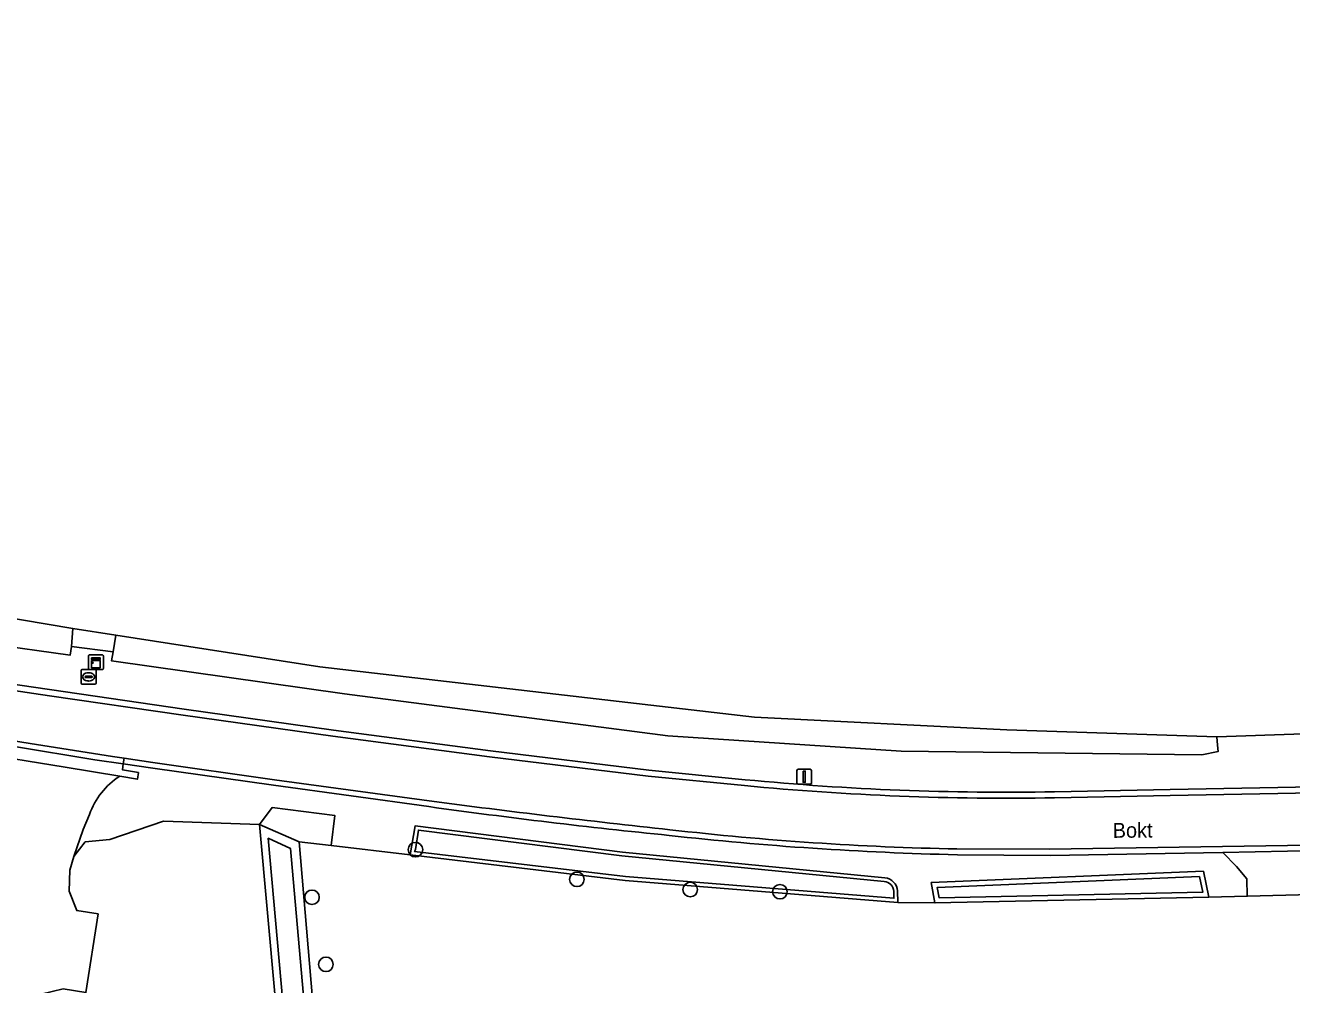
# Model space of a CAD drawing. Extents: x 162510 to 163918, y 388494 to 389774.
# Drawn here: x 162682.9 to 162767.9, y 389035.7 to 389100.2 of the extents above; entities that cross this region are included whole.
import ezdxf

# ---------------------------------------------------------------- set-up
doc = ezdxf.new("R2010")
doc.units = 0
for name, color, linetype in [('IMGEO_Boom', 7, 'Continuous'), ('IMGEO_Bouwland', 7, 'Continuous'), ('IMGEO_Duiker', 7, 'Continuous'), ('IMGEO_Erf', 7, 'Continuous'), ('IMGEO_Groenvoorziening', 7, 'Continuous'), ('IMGEO_Kast', 7, 'Continuous'), ('IMGEO_Lichtmast', 7, 'Continuous'), ('IMGEO_Oever', 7, 'Continuous'), ('IMGEO_Openbare_ruimte_label', 7, 'Continuous'), ('IMGEO_Rijbaan_lokaal_gesloten', 7, 'Continuous'), ('IMGEO_Rijbaan_lokaal_halfverhard', 7, 'Continuous'), ('IMGEO_Rijbaan_lokaal_onverhard', 7, 'Continuous'), ('IMGEO_Rioolput', 7, 'Continuous'), ('IMGEO_Voetpad_halfverhard', 7, 'Continuous'), ('IMGEO_Waterloop', 7, 'Continuous')]:
    doc.layers.add(name, color=color, linetype=linetype)

msp = doc.modelspace()

# ---------------------------------------------------------------- linework, layer by layer
at = {"layer": 'IMGEO_Boom'}
for centre in [(162709.078, 389044.8), (162719.925, 389042.806), (162702.13, 389041.6), (162727.531, 389042.116), (162733.555, 389041.974), (162703.062, 389037.094)]:
    msp.add_circle(centre, 0.489, dxfattribs=at)
at = {"layer": 'IMGEO_Bouwland'}
msp.add_lwpolyline([(162655.166, 389107.621), (162652.745, 389083.952), (162650.857, 389065.794), (162651.566, 389065.632), (162653.989, 389065.078), (162657.8, 389064.433), (162686.069, 389059.649), (162688.964, 389059.201), (162702.649, 389057.082), (162731.841, 389053.7), (162748.803, 389052.862), (162762.9, 389052.38), (162768.724, 389052.581), (162789.49, 389053.299), (162788.462, 389081.4), (162784.276, 389122.828)], dxfattribs=at)
at = {"layer": 'IMGEO_Duiker'}
msp.add_lwpolyline([(162688.779, 389058.094), (162685.973, 389058.455)], dxfattribs=at)
at = {"layer": 'IMGEO_Erf'}
for points in [[(162686.129, 389044.347), (162685.878, 389043.414), (162685.828, 389042.005), (162686.328, 389040.707), (162687.768, 389040.483), (162686.948, 389035.206), (162683.689, 389014.233), (162682.949, 389010.321), (162681.088, 389002.931), (162679.913, 388979.622), (162679.871, 388978.794), (162699.641, 388980.885), (162704.579, 388981.579), (162702.825, 389000), (162698.608, 389046.48), (162692.159, 389046.724), (162688.546, 389045.49), (162686.898, 389045.328)], [(162770.174, 389041.798), (162769.256, 389041.776), (162764.939, 389041.674), (162762.366, 389041.613), (162743.97, 389041.227), (162741.471, 389041.257), (162723.167, 389042.732), (162708.724, 389044.447), (162703.427, 389045.076), (162701.259, 389045.333), (162703.968, 389013.408), (162704.722, 389000), (162705.649, 388983.517), (162705.816, 388981.677), (162713.87, 388982.43), (162742.1, 388985.07), (162771.437, 388985.756), (162771.116, 389000)]]:
    msp.add_lwpolyline(points, close=True, dxfattribs=at)
at = {"layer": 'IMGEO_Groenvoorziening'}
for points in [[(162768.724, 389052.581), (162762.9, 389052.38), (162762.949, 389051.82), (162762.987, 389051.393), (162761.887, 389051.169), (162741.709, 389051.416), (162726.028, 389052.44), (162704.318, 389055.281), (162688.676, 389057.479), (162688.779, 389058.094), (162688.964, 389059.201), (162686.069, 389059.649), (162685.973, 389058.455), (162685.89, 389057.87), (162674.992, 389059.401)], [(162674.728, 389057.063), (162680.49, 389056.14), (162693.54, 389054.23), (162703.586, 389052.824), (162714.112, 389051.432), (162724.747, 389050.133), (162731.224, 389049.502)], [(162689.455, 389050.561), (162689.397, 389050.172), (162690.474, 389049.983), (162690.404, 389049.536), (162689.22, 389049.734)], [(162709.987, 389047.69), (162699.539, 389049.124), (162691.436, 389050.274), (162689.455, 389050.561)], [(162752, 389048.687), (162759.764, 389048.841), (162770.604, 389049.034), (162781.74, 389049.182), (162789.956, 389049.185)], [(162687.189, 389047.163), (162686.761, 389046.153), (162686.129, 389044.347), (162686.898, 389045.328), (162688.546, 389045.49), (162692.159, 389046.724), (162698.608, 389046.48), (162699.451, 389047.627), (162703.666, 389047.09), (162703.427, 389045.076), (162708.724, 389044.447), (162709.068, 389046.402), (162722.979, 389044.631), (162740.603, 389042.913)], [(162741.462, 389042.023), (162741.471, 389041.257), (162743.97, 389041.227), (162743.725, 389042.585), (162761.999, 389043.351), (162762.366, 389041.613), (162764.939, 389041.674), (162764.909, 389042.849), (162764.221, 389043.664), (162763.312, 389044.614), (162751.698, 389044.414), (162745.474, 389044.46)]]:
    msp.add_lwpolyline(points, dxfattribs=at)
for centre, radius, start, end in [((162691.981, 389045.465), 5.084, 122.89289, 160.4921), ((162748.686, 389229.414), 180.757, 264.45646, 271.05065), ((162768.785, 389469.713), 426.099, 262.06841, 264.25221), ((162750.452, 389264.126), 219.723, 263.63974, 268.70186), ((162740.509, 389041.963), 0.955, 3.61422, 84.35493)]:
    msp.add_arc(centre, radius, start, end, dxfattribs=at)
at = {"layer": 'IMGEO_Kast'}
for p, q in [((162687.12, 389056.969), (162687.12, 389057.81)), ((162687.12, 389057.81), (162687.12, 389056.969)), ((162687.195, 389057.894), (162688.036, 389057.894)), ((162688.036, 389057.894), (162687.195, 389057.894)), ((162688.12, 389057.819), (162688.12, 389056.978)), ((162688.12, 389056.978), (162688.12, 389057.819)), ((162688.045, 389056.894), (162687.204, 389056.894)), ((162687.204, 389056.894), (162688.045, 389056.894))]:
    msp.add_line(p, q, dxfattribs=at)
for points in [[(162687.315, 389057.684), (162687.915, 389057.684), (162687.915, 389057.599), (162687.315, 389057.599), (162687.315, 389057.684)], [(162687.315, 389057.509), (162687.915, 389057.509), (162687.915, 389057.02), (162687.315, 389057.02), (162687.315, 389057.509)]]:
    msp.add_lwpolyline(points, dxfattribs=at)
msp.add_circle((162687.399, 389057.358), 0.0377, dxfattribs=at)
for centre, start, end in [((162687.198, 389057.816), 92.4484, 184.28452), ((162687.198, 389057.816), 92.4484, 184.28452), ((162688.042, 389057.816), 2.4484, 94.28452), ((162688.042, 389057.816), 2.4484, 94.28452), ((162687.198, 389056.972), 182.4484, 274.28452), ((162687.198, 389056.972), 182.4484, 274.28452), ((162688.042, 389056.972), 272.4484, 4.28452), ((162688.042, 389056.972), 272.4484, 4.28452)]:
    msp.add_arc(centre, 0.0779, start, end, dxfattribs=at)
at = {"layer": 'IMGEO_Lichtmast'}
for p, q in [((162734.693, 389049.299), (162734.693, 389050.099)), ((162734.693, 389050.099), (162734.693, 389049.299)), ((162734.793, 389050.199), (162735.583, 389050.199)), ((162735.583, 389050.199), (162734.793, 389050.199)), ((162735.683, 389050.099), (162735.683, 389049.299)), ((162735.683, 389049.299), (162735.683, 389050.099)), ((162735.583, 389049.199), (162734.793, 389049.199)), ((162734.793, 389049.199), (162735.583, 389049.199))]:
    msp.add_line(p, q, dxfattribs=at)
msp.add_lwpolyline([(162735.113, 389050.074), (162735.263, 389050.074), (162735.263, 389049.324), (162735.113, 389049.324), (162735.113, 389050.074)], dxfattribs=at)
for centre, start, end in [((162734.793, 389050.099), 90, 180), ((162734.793, 389050.099), 90, 180), ((162735.583, 389050.099), 0, 90), ((162735.583, 389050.099), 360, 90), ((162734.793, 389049.299), 180, 270), ((162734.793, 389049.299), 180, 270), ((162735.583, 389049.299), 270, 0), ((162735.583, 389049.299), 270, 0)]:
    msp.add_arc(centre, 0.1, start, end, dxfattribs=at)
at = {"layer": 'IMGEO_Oever'}
for points in [[(162705.816, 388981.677), (162705.649, 388983.517), (162704.722, 389000), (162703.968, 389013.408), (162701.259, 389045.333), (162698.608, 389046.48), (162702.825, 389000), (162704.579, 388981.579), (162706.158, 388965), (162707.976, 388947.833), (162710.495, 388931.566), (162710.671, 388930.424), (162711.044, 388928.019), (162711.565, 388924.584), (162711.866, 388922.595), (162714.157, 388913.171), (162713.16, 388922.287), (162713.097, 388922.665), (162712.193, 388928.079), (162711.78, 388930.55), (162711.59, 388931.691), (162708.895, 388947.83), (162706.857, 388970.231)], [(162711.298, 388931.911), (162711.89, 388928.028), (162712.794, 388922.614), (162712.856, 388922.245), (162713.337, 388917.847), (162712.168, 388922.654), (162711.869, 388924.63), (162711.348, 388928.066), (162710.707, 388931.844), (162708.226, 388947.866), (162706.409, 388965.025), (162703.271, 388999.989), (162699.196, 389045.568), (162700.691, 389044.874), (162703.453, 389013.379), (162704.285, 388999.944), (162705.193, 388983.485), (162705.406, 388981.634), (162706.606, 388970.208), (162708.645, 388947.798)], [(162761.999, 389043.351), (162743.725, 389042.585), (162743.97, 389041.227), (162762.366, 389041.613)], [(162761.73, 389043.004), (162761.955, 389041.939), (162744.249, 389041.568), (162744.123, 389042.266)]]:
    msp.add_lwpolyline(points, close=True, dxfattribs=at)
for points in [[(162740.603, 389042.913), (162722.979, 389044.631), (162709.068, 389046.402), (162708.724, 389044.447), (162723.167, 389042.732), (162741.471, 389041.257), (162741.462, 389042.023)], [(162741.206, 389042.003), (162741.212, 389041.535), (162723.192, 389042.987), (162709.023, 389044.669), (162709.078, 389044.8), (162709.278, 389046.117), (162722.95, 389044.377), (162740.568, 389042.659)]]:
    msp.add_lwpolyline(points, dxfattribs=at)
for radius, start, end in [(0.955, 3.61422, 84.35493), (0.698, 3.26245, 85.14365)]:
    msp.add_arc((162740.509, 389041.963), radius, start, end, dxfattribs=at)
at = {"layer": 'IMGEO_Rijbaan_lokaal_gesloten'}
for points in [[(162731.185, 389049.104), (162724.699, 389049.736), (162714.06, 389051.035), (162703.531, 389052.428), (162693.483, 389053.834), (162684.499, 389055.134), (162680.427, 389055.745), (162674.666, 389056.668)], [(162666.117, 389054.911), (162672.393, 389053.755), (162677.364, 389052.884), (162683.195, 389051.941), (162688.731, 389051.06), (162689.512, 389050.943), (162691.443, 389050.652), (162699.62, 389049.498), (162710.01, 389048.078)], [(162789.956, 389048.785), (162781.745, 389048.782), (162770.611, 389048.634), (162759.772, 389048.441), (162752.007, 389048.287)], [(162745.45, 389044.849), (162751.665, 389044.823), (162767.648, 389045.079), (162778.413, 389045.316)]]:
    msp.add_lwpolyline(points, dxfattribs=at)
for centre, radius, start, end in [((162748.696, 389229.646), 181.389, 264.46014, 271.0459), ((162795.113, 389689.922), 647.461, 262.447132, 263.887178), ((162749.336, 389247.236), 202.424, 263.42766, 268.90001)]:
    msp.add_arc(centre, radius, start, end, dxfattribs=at)
at = {"layer": 'IMGEO_Rijbaan_lokaal_halfverhard'}
for points in [[(162674.666, 389056.668), (162680.427, 389055.745), (162684.499, 389055.134), (162693.483, 389053.834), (162703.531, 389052.428), (162714.06, 389051.035), (162724.699, 389049.736), (162731.185, 389049.104)], [(162731.224, 389049.502), (162724.747, 389050.133), (162714.112, 389051.432), (162703.586, 389052.824), (162693.54, 389054.23), (162680.49, 389056.14), (162674.728, 389057.063)], [(162666.038, 389054.524), (162672.306, 389053.366), (162675.204, 389052.865), (162677.242, 389052.512), (162682.152, 389051.732), (162687.557, 389050.846), (162689.455, 389050.561), (162689.512, 389050.943), (162688.731, 389051.06), (162683.195, 389051.941), (162677.364, 389052.884), (162672.393, 389053.755), (162666.117, 389054.911)], [(162689.512, 389050.943), (162689.455, 389050.561), (162691.436, 389050.274), (162699.539, 389049.124), (162709.987, 389047.69)], [(162710.01, 389048.078), (162699.62, 389049.498), (162691.443, 389050.652), (162689.512, 389050.943)], [(162789.956, 389049.185), (162781.74, 389049.182), (162770.604, 389049.034), (162759.764, 389048.841), (162752, 389048.687)], [(162752.007, 389048.287), (162759.772, 389048.441), (162770.611, 389048.634), (162781.745, 389048.782), (162789.956, 389048.785)], [(162778.413, 389045.316), (162767.648, 389045.079), (162751.665, 389044.823), (162745.45, 389044.849)], [(162745.474, 389044.46), (162751.698, 389044.414), (162763.312, 389044.614), (162767.647, 389044.689), (162770.277, 389044.748), (162778.415, 389044.929)]]:
    msp.add_lwpolyline(points, dxfattribs=at)
msp.add_lwpolyline([(162677.242, 389052.512), (162677.171, 389052.087), (162679.523, 389051.729), (162679.462, 389051.327), (162685.553, 389050.347), (162689.22, 389049.734), (162690.404, 389049.536), (162690.474, 389049.983), (162689.397, 389050.172), (162689.455, 389050.561), (162687.557, 389050.846), (162682.152, 389051.732)], close=True, dxfattribs=at)
for centre, radius, start, end in [((162748.696, 389229.646), 181.389, 264.46014, 271.0459), ((162748.686, 389229.414), 180.757, 264.45646, 271.05065), ((162795.113, 389689.922), 647.461, 262.447132, 263.887178), ((162768.785, 389469.713), 426.099, 262.06841, 264.25221), ((162750.452, 389264.126), 219.723, 263.63974, 268.70186), ((162749.336, 389247.236), 202.424, 263.42766, 268.90001)]:
    msp.add_arc(centre, radius, start, end, dxfattribs=at)
at = {"layer": 'IMGEO_Rijbaan_lokaal_onverhard'}
for points in [[(162689.22, 389049.734), (162685.553, 389050.347), (162679.462, 389051.327), (162679.523, 389051.729), (162677.171, 389052.087), (162677.242, 389052.512), (162675.204, 389052.865), (162678.161, 389051.594)], [(162683.939, 389035.1), (162685.42, 389035.444), (162686.948, 389035.206), (162687.768, 389040.483), (162686.328, 389040.707), (162685.828, 389042.005), (162685.878, 389043.414), (162686.129, 389044.347), (162686.761, 389046.153), (162687.189, 389047.163)]]:
    msp.add_lwpolyline(points, dxfattribs=at)
msp.add_arc((162691.981, 389045.465), 5.084, 122.89289, 160.4921, dxfattribs=at)
at = {"layer": 'IMGEO_Rioolput'}
for p, q in [((162686.625, 389055.986), (162686.625, 389056.838)), ((162686.7, 389056.912), (162687.552, 389056.912)), ((162686.884, 389056.406), (162686.884, 389056.418)), ((162686.927, 389056.455), (162687.325, 389056.455)), ((162687.113, 389056.692), (162687.138, 389056.692)), ((162687.368, 389056.418), (162687.368, 389056.406)), ((162687.626, 389056.838), (162687.626, 389055.986)), ((162687.552, 389055.912), (162686.7, 389055.912)), ((162687.322, 389056.369), (162686.924, 389056.369)), ((162687.136, 389056.132), (162687.111, 389056.132))]:
    msp.add_line(p, q, dxfattribs=at)
for points in [[(162686.625, 389055.986), (162686.625, 389056.838)], [(162686.7, 389056.912), (162687.552, 389056.912)], [(162687.626, 389056.838), (162687.626, 389055.986)], [(162687.552, 389055.912), (162686.7, 389055.912)]]:
    msp.add_lwpolyline(points, dxfattribs=at)
for centre, radius, start, end in [((162686.702, 389056.836), 0.0765, 91.55205, 178.44795), ((162686.702, 389056.836), 0.0765, 91.55205, 178.44795), ((162686.924, 389056.415), 0.0403, 85.87752, 175.75265), ((162687.329, 389056.417), 0.0386, 1.73085, 96.63898), ((162687.55, 389056.836), 0.0765, 1.55205, 88.44795), ((162687.55, 389056.836), 0.0765, 1.55205, 88.44795), ((162686.702, 389055.988), 0.0765, 181.55205, 268.44795), ((162686.702, 389055.988), 0.0765, 181.55205, 268.44795), ((162686.921, 389056.405), 0.0366, 178.93798, 274.71019), ((162687.325, 389056.412), 0.043, 264.86636, 352.45326), ((162687.55, 389055.988), 0.0765, 271.55205, 358.44795), ((162687.55, 389055.988), 0.0765, 271.55205, 358.44795)]:
    msp.add_arc(centre, radius, start, end, dxfattribs=at)
for centre, major_axis, ratio, start_param, end_param in [((162687.112, 389056.412), (-0.387, 0.002), 0.722429, 4.712389, 7.853982), ((162687.137, 389056.412), (-0.39, 0.002), 0.717154, 1.570796, 4.712389)]:
    msp.add_ellipse(centre, major_axis=major_axis, ratio=ratio, start_param=start_param, end_param=end_param, dxfattribs=at)
at = {"layer": 'IMGEO_Voetpad_halfverhard'}
msp.add_lwpolyline([(162769.539, 389044.044), (162770.277, 389044.748), (162767.647, 389044.689), (162763.312, 389044.614), (162764.221, 389043.664), (162764.909, 389042.849), (162764.939, 389041.674), (162769.256, 389041.776), (162769.222, 389043.146)], close=True, dxfattribs=at)
at = {"layer": 'IMGEO_Waterloop'}
for points in [[(162686.069, 389059.649), (162657.8, 389064.433), (162653.989, 389065.078), (162651.566, 389065.632), (162650.857, 389065.794), (162649.957, 389066), (162649.111, 389066.053), (162648.82, 389065.815), (162648.795, 389065.73), (162648.635, 389065.18), (162648.74, 389064.73), (162649.522, 389064.403), (162651.193, 389063.981), (162653.814, 389063.319), (162655.254, 389062.955), (162657.545, 389062.618), (162658.351, 389062.5), (162674.992, 389059.401), (162685.89, 389057.87), (162685.973, 389058.455)], [(162702.649, 389057.082), (162688.964, 389059.201), (162688.779, 389058.094), (162688.676, 389057.479), (162704.318, 389055.281), (162726.028, 389052.44), (162741.709, 389051.416), (162761.887, 389051.169), (162762.987, 389051.393), (162762.949, 389051.82), (162762.9, 389052.38), (162748.803, 389052.862), (162731.841, 389053.7)], [(162703.427, 389045.076), (162703.666, 389047.09), (162699.451, 389047.627), (162698.608, 389046.48), (162701.259, 389045.333)], [(162704.285, 388999.944), (162703.453, 389013.379), (162700.691, 389044.874), (162699.196, 389045.568), (162703.271, 388999.989), (162706.409, 388965.025), (162708.226, 388947.866), (162710.707, 388931.844), (162711.348, 388928.066), (162711.869, 388924.63), (162712.168, 388922.654), (162713.337, 388917.847), (162712.856, 388922.245), (162712.794, 388922.614), (162711.89, 388928.028), (162711.298, 388931.911), (162708.645, 388947.798), (162706.606, 388970.208), (162705.406, 388981.634), (162705.193, 388983.485)], [(162761.73, 389043.004), (162744.123, 389042.266), (162744.249, 389041.568), (162761.955, 389041.939)]]:
    msp.add_lwpolyline(points, close=True, dxfattribs=at)
msp.add_lwpolyline([(162740.568, 389042.659), (162722.95, 389044.377), (162709.278, 389046.117), (162709.078, 389044.8), (162709.023, 389044.669), (162723.192, 389042.987), (162741.212, 389041.535), (162741.206, 389042.003)], dxfattribs=at)
msp.add_arc((162740.509, 389041.963), 0.698, 3.26245, 85.14365, dxfattribs=at)

# ---------------------------------------------------------------- texts
at = {"layer": 'IMGEO_Openbare_ruimte_label'}
msp.add_text('Bokt', height=1, rotation=0.51565, dxfattribs=at).set_placement((162755.911, 389045.592))

doc.saveas('drawing.dxf')
